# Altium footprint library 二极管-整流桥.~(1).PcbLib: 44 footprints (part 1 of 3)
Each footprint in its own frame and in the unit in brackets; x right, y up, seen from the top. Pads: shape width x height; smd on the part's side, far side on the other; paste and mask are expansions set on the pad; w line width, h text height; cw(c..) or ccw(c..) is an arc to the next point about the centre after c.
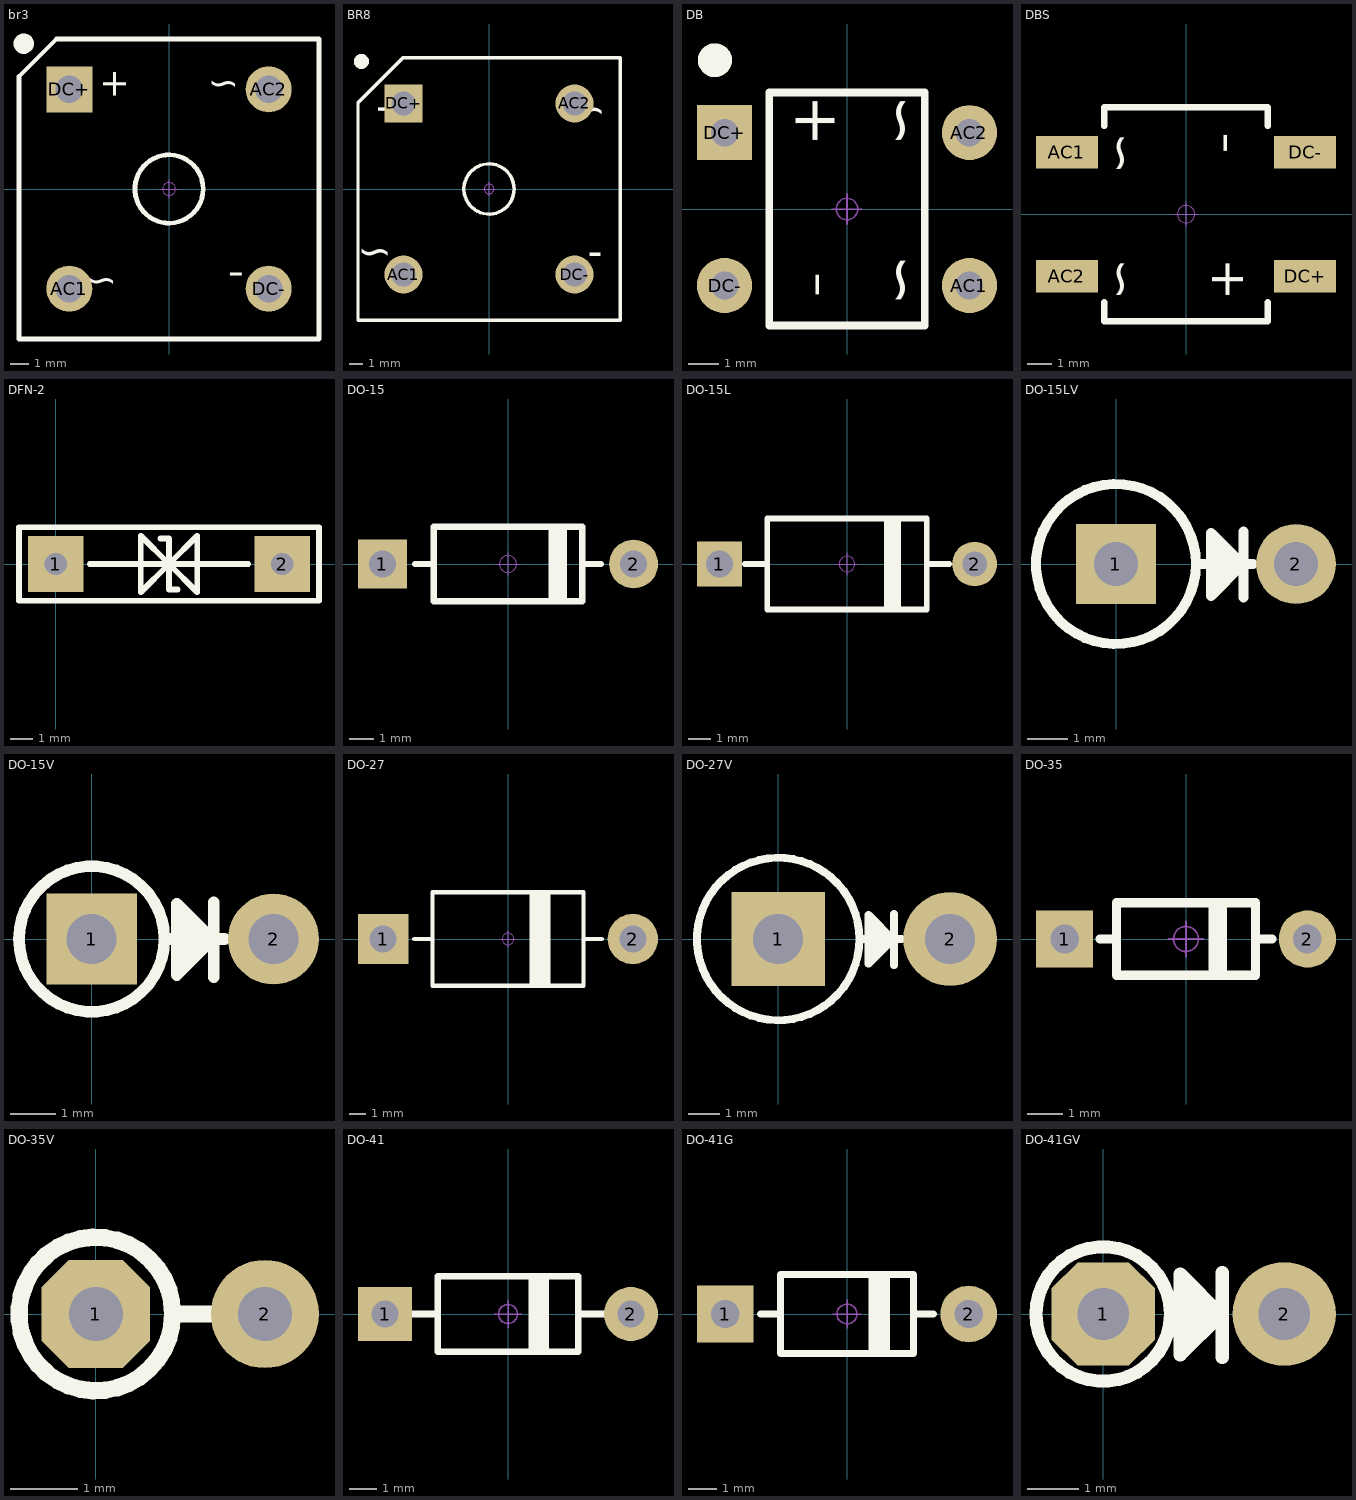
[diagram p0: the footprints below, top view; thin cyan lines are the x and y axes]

## br3 [mm] "18*7.1mm(宽高)"
pads (4):
  round 2.5 hole 1.5: AC1(-5.4,-5.4) AC2(5.4,5.4) DC-(5.4,-5.4)
  rect 2.5x2.5 hole 1.5: DC+(-5.4,5.4)
Top Overlay:
  circle w0.6: c-7.874,7.874 r0.254
  circle w0.254: c0,0 r1.85
  lines w0.254: -8.128,-8.128 8.128,-8.128 8.128,8.128 -6.096,8.128 -8.128,6.096 -8.128,-8.128
  text "~" at -2.794,-6.096 h2.54
  text "~" at 3.81,4.572 h2.54
  text "-" at 4.064,-5.842 h3.05
  text "+" at -4.064,4.826 h2.54
Mechanical 15:
  circle w0.05: c0,0 r0.35
  lines w0.05: -0.5,0 0.5,0 ; 0,-0.5 0,0.5
3D body: height 6, standoff -3.5, extent -8,-8 8,8

## BR8 [mm] "16*8mm(宽高)"
pads (4):
  round 2.8 hole 1.8: AC1(-6.3,-6.3) AC2(6.3,6.3) DC-(6.3,-6.3)
  rect 2.8x2.8 hole 1.8: DC+(-6.3,6.3)
Top Overlay:
  circle w0.254: c0,0 r1.85
  circle w0.6: c-9.398,9.398 r0.254
  lines w0.254: -9.652,-9.652 -9.652,6.35 -6.35,9.652 9.652,9.652 9.652,-9.652 -9.652,-9.652
  text "+" at -8.89,4.572 h3.81
  text "-" at 8.382,-6.35 h3.81
  text "~" at 8.636,4.064 h3.81
  text "~" at -7.112,-6.35 h3.81
Mechanical 15:
  circle w0.05: c0,0 r0.35
  lines w0.05: -0.5,0 0.5,0 ; 0,-0.5 0,0.5
3D body: height 7.1, standoff -3.5, extent -9.45,-9.45 9.45,9.45

## DB [mm] "8.5*7.6*3mm(长宽高)"
pads (4):
  round 1.8 hole 0.9: AC1(4.004,-2.5) AC2(4.004,2.5) DC-(-4.004,-2.5)
  rect 1.8x1.8 hole 0.9: DC+(-4.004,2.5)
Top Overlay:
  circle w0.6: c-4.318,4.866 r0.254
  lines w0.254: -2.54,-3.81 -2.54,3.81 2.54,3.81 2.54,-3.81 -2.54,-3.81
  text "+" at -2.159,2.032 h2.54
  text "-" at -2.159,-2.921 h3.05
  text "~" at 0.635,2.032 h2.54
  text "~" at 0.635,-3.175 h2.54
Mechanical 15:
  circle w0.05: c0,0 r0.35
  lines w0.05: -0.5,0 0.5,0 ; 0,-0.5 0,0.5
3D body: height 3.2, standoff -3.01, extent -4.436,-4.25 4.436,4.25

## DBS [mm] "8.5*10.1*3mm(长宽高)"
height 12.3
pads (4):
  rect 2.5x1.3 smd: AC1(-4.8,2.5) AC2(-4.8,-2.5) DC+(4.8,-2.5) DC-(4.8,2.5)
Top Overlay:
  lines w0.254: -3.302,-3.556 -3.302,-4.318 3.302,-4.318 3.302,-3.556 ; -3.302,3.556 -3.302,4.318 3.302,4.318 3.302,3.556
  text "~" at -1.524,3.302 h2.54
  text "~" at -1.524,-1.778 h2.54
  text "-" at 2.794,3.302 h3.05
  text "+" at 2.794,-1.778 h2.54
Mechanical 15:
  circle w0.05: c0,0 r0.35
  lines w0.05: -0.5,0 0.5,0 ; 0,-0.5 0,0.5
3D body: height 3.1, standoff -0.03, extent -5.05,-4.25 5.05,4.25

## DFN-2 [mm] "1.0*0.6(长*宽）"
pads (2):
  rect 2.5x2.5 hole 1: 1(0,0) 2(10.16,0)
Top Overlay:
  lines w0.254: 1.524,0 8.636,0 ; 4.699,1.143 5.08,1.143 5.08,-1.143 5.461,-1.143 ; 5.08,0 3.81,-1.27 3.81,1.27 5.08,0 ; 5.08,0 6.35,-1.27 6.35,1.27 5.08,0 ; -1.651,-1.651 -1.651,1.651 11.811,1.651 11.811,-1.651 -1.651,-1.651

## DO-15 [mm] "3.3*10.3mm(直径，脚距）"
pads (2):
  rect 2x2 hole 1.1: 1(-5.15,0)
  round 2 hole 1.1: 2(5.15,0)
Top Overlay:
  lines w0.254: -3.81,0 -3.048,0 ; 1.778,-1.524 1.778,1.524 ; 2.032,-1.524 2.032,1.524 ; 2.286,-1.524 2.286,1.524 ; 3.048,0 3.81,0 ; -3.048,-1.524 3.048,-1.524 3.048,1.524 -3.048,1.524 -3.048,-1.524
Mechanical 15:
  circle w0.05: c0,0 r0.35
  lines w0.05: -0.5,0 0.5,0 ; 0,-0.5 0,0.5
3D body: height 3.35, standoff -3.45, extent -5.55,-1.651 5.55,1.651

## DO-15L [mm] "4*11.4mm(直径，脚距）"
pads (2):
  rect 2x2 hole 1.2: 1(-5.7,0)
  round 2 hole 1.1: 2(5.7,0)
Top Overlay:
  lines w0.254: -4.572,0 -3.556,0 ; 1.778,-2.032 1.778,2.032 ; 2.032,-2.032 2.032,2.032 ; 2.286,-2.032 2.286,2.032 ; 3.556,0 4.572,0 ; -3.556,-2.032 3.556,-2.032 3.556,2.032 -3.556,2.032 -3.556,-2.032
Mechanical 15:
  circle w0.05: c0,0 r0.35
  lines w0.05: -0.5,0 0.5,0 ; 0,-0.5 0,0.5
3D body: height 4.05, standoff -3.45, extent -6.1,-2.001 6.1,2.001

## DO-15LV [mm] "4*4.5mm(直径，脚距）"
pads (2):
  rect 2x2 hole 1.1: 1(0,0)
  round 2 hole 1.1: 2(4.5,0)
Top Overlay:
  circle w0.254: c0,0 r2
  lines w0.254: 2.108,0 3.429,0 ; 2.54,0.559 2.565,-0.432 3.048,0 2.794,0.254 2.794,0 2.794,-0.254 ; 3.15,-0.02 2.377,-0.792 2.377,0.775 3.19,-0.038 ; 3.19,-0.841 3.19,0.805
3D body: height 9.45, standoff -3.45, extent -2.001,-2.001 4.9,2.001

## DO-15V [mm] "3.3*4mm(直径，脚距）"
pads (2):
  rect 2x2 hole 1.1: 1(0,0)
  round 2 hole 1.1: 2(4,0)
Top Overlay:
  circle w0.254: c0,0 r1.6
  lines w0.254: 1.6,0 2.921,0 ; 2.032,0.559 2.057,-0.432 2.54,0 2.286,0.254 2.286,0 2.286,-0.254 ; 2.642,-0.02 1.869,-0.792 1.869,0.775 2.682,-0.038 ; 2.682,-0.841 2.682,0.805
3D body: height 8.35, standoff -3.45, extent -1.651,-1.651 4.4,1.651

## DO-27 [mm] "5.2*14.9mm(直径，脚距）"
pads (2):
  rect 3x3 hole 1.6: 1(-7.45,0)
  round 3 hole 1.6: 2(7.45,0)
Top Overlay:
  rectangle: 1.27,-2.794 2.54,2.794
  lines w0.254: -5.588,0 -4.572,0 ; 4.572,0 5.588,0 ; -4.5,-2.794 -4.5,2.794 4.5,2.794 4.5,-2.794 -4.5,-2.794
Mechanical 15:
  circle w0.05: c0,0 r0.35
  lines w0.05: -0.5,0 0.5,0 ; 0,-0.5 0,0.5
3D body: height 5.25, standoff -3.46, extent -8.1,-2.601 8.1,2.601

## DO-27V [mm] "5.2*5.5mm(直径，脚距）"
pads (2):
  rect 3x3 hole 1.6: 1(0,0)
  round 3 hole 1.6: 2(5.5,0)
Top Overlay:
  circle w0.254: c0,0 r2.6
  lines w0.254: 2.616,0 3.698,0 ; 3.048,0.559 3.073,-0.432 3.556,0 ; 3.302,-0.254 3.302,0 3.302,0.254 3.556,0 ; 3.658,-0.02 2.885,-0.792 2.885,0.775 3.698,-0.038 ; 3.698,-0.841 3.698,0.805 ; 3.937,0 3.556,0
3D body: height 11.7, standoff -3.46, extent -2.601,-2.601 6.15,2.601

## DO-35 [mm] "1.8*6.8mm(直径，脚距）"
pads (2):
  rect 1.6x1.6 hole 0.8: 1(-3.4,0)
  round 1.6 hole 0.8: 2(3.4,0)
Top Overlay:
  rectangle: 0.635,-1.016 1.143,1.016
  lines w0.254: -2.413,0 -1.95,0 ; 1.95,0 2.413,0 ; -1.95,-1.016 -1.95,1.016 1.95,1.016 1.95,-1.016 -1.95,-1.016
Mechanical 15:
  circle w0.05: c0,0 r0.35
  lines w0.05: -0.5,0 0.5,0 ; 0,-0.5 0,0.5
3D body: height 1.85, standoff -3.45, extent -3.65,-0.901 3.65,0.901

## DO-35V [mm] "1.8*2.5mm(直径，脚距）"
pads (2):
  oct 1.6x1.6 hole 0.8: 1(0,0)
  round 1.6 hole 0.8: 2(2.5,0)
Top Overlay:
  circle w0.254: c0,0 r1.136
  lines w0.254: 1.136,0 1.778,0
3D body: height 5.15, standoff -3.5, extent -0.901,-0.901 2.75,0.901

## DO-41 [mm] "2.6*9.1mm(直径，脚距）"
height 2.4
pads (2):
  rect 2x2 hole 1: 1(-4.55,0)
  round 2 hole 1: 2(4.55,0)
Top Overlay:
  rectangle: 0.762,-1.397 1.524,1.397
  lines w0.254: -3.556,0 -2.6,0 ; 2.6,0 3.556,0 ; -2.6,-1.397 -2.6,1.397 2.6,1.397 2.6,-1.397 -2.6,-1.397
Mechanical 15:
  circle w0.05: c0,0 r0.35
  lines w0.05: -0.5,0 0.5,0 ; 0,-0.5 0,0.5
3D body: height 2.65, standoff -3.45, extent -4.925,-1.288 4.975,1.314

## DO-41G [mm] "2.5*8.6mm(直径，脚距）"
height 2.4
pads (2):
  rect 2x2 hole 1: 1(-4.3,0)
  round 2 hole 1: 2(4.3,0)
Top Overlay:
  rectangle: 0.762,-1.397 1.524,1.397
  lines w0.254: -3.048,0 -2.346,0 ; 2.346,0 3.048,0 ; -2.35,-1.397 -2.35,1.397 2.35,1.397 2.35,-1.397 -2.35,-1.397
Mechanical 15:
  circle w0.05: c0,0 r0.35
  lines w0.05: -0.5,0 0.5,0 ; 0,-0.5 0,0.5
3D body: height 2.55, standoff -3.45, extent -4.7,-1.251 4.7,1.251

## DO-41GV [mm] "2.5*3.5mm(直径，脚距）"
height 2.4
pads (2):
  oct 2x2 hole 1: 1(0,0)
  round 2 hole 1: 2(3.5,0)
Top Overlay:
  circle w0.254: c0,0 r1.3
  lines w0.254: 1.651,0.559 1.676,-0.432 2.159,0 1.905,0.254 1.905,0 1.905,-0.254 ; 2.261,-0.02 1.488,-0.792 1.488,0.775 2.301,-0.038 ; 2.301,-0.841 2.301,0.805
3D body: height 6.4, standoff -3.5, extent -1.251,-1.251 3.9,1.251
